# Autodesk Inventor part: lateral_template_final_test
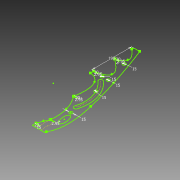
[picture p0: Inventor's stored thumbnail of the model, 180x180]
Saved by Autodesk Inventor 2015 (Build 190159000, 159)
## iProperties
Created: 2017-04
Part Number: lateral_template_final_test
Material: Generic
Document SubType Name: Modeling
Designer: mcalderon
Density: 1 g/cm^3
Appearance: Default
Author: mcalderon
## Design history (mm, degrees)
sketch "Sketch1"
  geometry: L1 (85, -199.4)-(85, -202.35); L2 (125, -149.4)-(125, -152.35); L3 (125, -149.4)-(105, -149.4); L4 (105, -152.35)-(125, -152.35); L5 (64.5, 2.549)-(64.5, -0.401); L6 (84.5, 2.549)-(84.5, -0.401); L7 (84.5, 2.549)-(64.5, 2.549); L8 (64.5, -0.401)-(84.5, -0.401); L9 (8, 152.95)-(8, 150); L10 (28, 152.95)-(28, 150); L11 (28, 152.95)-(8, 152.95); L12 (8, 150)-(28, 150); L13 (145, -210)-(145, -217.35); L14 (8, 136.93)-(8, 150); L15 (105, -149.4)-(105, -152.35); L16 (8, 251.475)-(28, 251.475); L17 (28, 251.475)-(28, 254.425); L18 (28, 254.425)-(8, 254.425); L19 (8, 254.425)-(8, 251.475); L20 (8, 342.95)-(36.571, 342.95); L21 (8, 251.475)-(8, 254.425); L22 (8, 334.129)-(8, 342.95); L23 (85, -217.35)-(145, -217.35); L24 (105, -152.35)-(105, -217.35); L25 (125, -152.35)-(125, -217.35); L26 (105, -199.4)-(85, -199.4); L27 (85, -202.35)-(105, -202.35); L28 (85, -202.35)-(85, -217.35); L29 (105, -199.4)-(105, -202.35); C1 r 7.5 at (50.685, 254.425); C2 r 7.5 at (50.685, 150); C3 r 7.5 at (78.994, 150); C4 r 7.5 at (95.898, 74.582); C5 r 7.5 at (125, -73.095); A1 r 159.164 centre (-37.491, 6.123) between (115, -39.483) and (65, 127.897); A2 r 168.504 centre (-37.491, 6.123) between (123.948, -42.159) and (71.014, 135.042); A3 r 149.824 centre (-37.491, 6.123) between (106.052, -36.807) and (58.986, 120.751); A4 r 9.34 centre (115, -39.483) between (106.052, -36.807) and (123.948, -42.159); A5 r 9.34 centre (65, 127.897) between (71.014, 135.042) and (58.986, 120.751); 8 further points; 1 other entity
  constraints: 59 end point, 10 centre point, 10 point on circle, 8 perpendicular, 6 horizontal, 5 parallel, 5 point on line, 5 vertical, 4 tangent, 1 collinear, 24 other
  dimensions: "d14" = 20 distance between parallel lines of L6 L5; "d16" = 20 distance between parallel lines of L10 L9; "d22" = 2.95 distance between parallel lines of L4 L3; "d23" = 2.95 distance between parallel lines of L8 L7; "d24" = 2.95 distance between parallel lines of L12 L11; "d26" = 190 distance of L9.start L20.start; "d29" = 20 distance of L18.end L17.end; "d30" = 2.95 distance of L17.end L16.end; "d31" = 15 diameter of C1; "d32" = 15 diameter of C2; "d33" = 15 diameter of C3; "d34" = 15 diameter of C4; "d35" = 15 diameter of C5; "d38" = 20 distance of L26.start L1.start; "d39" = 15 distance between parallel lines of L23 L27
